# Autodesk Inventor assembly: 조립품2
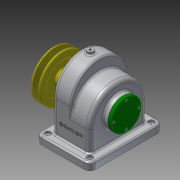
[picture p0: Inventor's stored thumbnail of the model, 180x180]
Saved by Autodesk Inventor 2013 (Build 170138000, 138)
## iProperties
Created: 2017-11
Part Number: 조립품2
Document SubType Name: Assembly
Designer: Administrator
Author: Administrator
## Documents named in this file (14)
- C:\Users\Administrator\Desktop\새 폴더\답안조립품.iam
- C:\Users\Administrator\Desktop\새 폴더\본체.ipt
- C:\Users\Administrator\Desktop\새 폴더\축.ipt
- C:\Users\Administrator\Desktop\새 폴더\앞커버.ipt
- C:\Users\Administrator\Desktop\새 폴더\뒤커버.ipt
- C:\Users\Administrator\Desktop\새 폴더\스퍼기어.ipt
- C:\Users\Administrator\Desktop\새 폴더\볼트 M3 x 8.ipt
- C:\Users\Administrator\Desktop\새 폴더\키 - 6 x 6 x 22.ipt
- C:\Users\Administrator\Desktop\새 폴더\키 - 5 x 5 x 18.ipt
- C:\Users\Administrator\Desktop\새 폴더\멈춤나사 - M4 x 10.ipt
- 멈춤나사 - M4 x 10.ipt
- C:\Users\Administrator\Desktop\새 폴더\V-벨트풀리.ipt
- C:\Users\Administrator\Desktop\새 폴더\베어링 6002.ipt
- C:\Users\Administrator\Desktop\새 폴더\오일 실 15 30 7.ipt
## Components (1 placed, 1 different names)
1. V-벨트풀리:1
